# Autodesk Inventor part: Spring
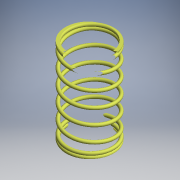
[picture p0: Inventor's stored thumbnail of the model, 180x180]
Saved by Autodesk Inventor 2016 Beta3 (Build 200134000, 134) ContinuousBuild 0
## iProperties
Shininess: 24.0
Compacted: True
Length Units: 11272
Angle Units: 11279
Time Units: 11290
Mass Units: 11286
Length Display Precision: 4
Angle Display Precision: 2
Company: Autodesk
Created: 2000-03
Part Number: Spring
Project: Inventor Samples
User Status: IN PROGRESS
Document SubType Name: Modeling
Designer: Autodesk, Inc.
Density: 8.03 g/cm^3
Material: Stainless Steel, Austenitic
Mass: 2.926 g
Surface Area: 14.1446 cm^2
Volume: 0.364384 cm^3
Appearance: Black
Density: 0.0
Volumn: 0.0
Area: 0.0
PropertySet Name: Model Information
Control State: 0
Master: False
Checked Out: False
Author: Autodesk, Inc.
Revision Number: A
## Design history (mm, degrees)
sketch "Sketch2"
  geometry: L1 (-14.979, -10.854)-(-14.979, 14.546); A1 r 0.546 centre (-22.51, -11.4) between (-21.964, -11.4) and (-22.51, -10.854); 1 further point
  constraints: 2 end point, 2 horizontal alignment, 2 point on circle, 2 vertical alignment, 1 centre point, 1 vertical, 5 other
  dimensions: "d0" = 25.4 distance of L1.start L1.end; "d1" = 13.97 diameter of A1.start L1; "d2" = 1.0922 diameter of A1
node "Coil1" dims "d3" = 3.175 (= 0.125 x d0), "d4" = 25.4, "d5" = 50, "d6" = 0, "d7" = 30 deg, "d8" = 1 deg, "d9" = 30 deg, "d10" = 1 deg
workaxis "Work Axis1"
node "Coil2" dims "d11" = 1.1176 (computed from d2), "d12" = 25.4, "d13" = 20, "d14" = 0, "d15" = 90 deg, "d16" = 90 deg, "d17" = 0, "d18" = 0
  sketch "Sketch3"
    geometry: L1 (7.531, -5.981)-(7.531, 31.384) reference; C1 r 0.546 at (0, 0) reference
node "Extrusion1" dims "d19" = 25.4, "d20" = 0
  sketch "Sketch4"
    geometry: L1 (-2.213, -5.605)-(17.486, -5.605); L2 (17.486, -5.605)-(17.486, 0.546); L3 (17.486, 0.546)-(-2.213, 0.546); L4 (-2.213, 0.546)-(-2.213, -5.605); C1 r 0.546 at (0, 0) reference
    constraints: 8 end point, 2 parallel, 1 horizontal, 1 perpendicular, 1 tangent
node "Coil3" dims "d21" = 1.1176 (computed from d2), "d22" = 25.4, "d23" = 20, "d24" = 0, "d25" = 90 deg, "d26" = 90 deg, "d27" = 0, "d28" = 0
  sketch "Sketch5"
    geometry: L1 (-7.531, -31.381)-(-7.531, 5.984) reference; C1 r 0.546 at (0, 0) reference
node "Extrusion2" dims "d29" = 25.4, "d30" = 0
  sketch "Sketch6"
    geometry: L1 (7.067, 10.583)-(-19.265, 10.583); L2 (-19.265, 10.583)-(-19.265, -0.546); L3 (-19.265, -0.546)-(7.067, -0.546); L4 (7.067, -0.546)-(7.067, 10.583); C1 r 0.546 at (0, 0) reference
    constraints: 8 end point, 2 parallel, 1 horizontal, 1 perpendicular, 1 tangent
body "Solid1"
